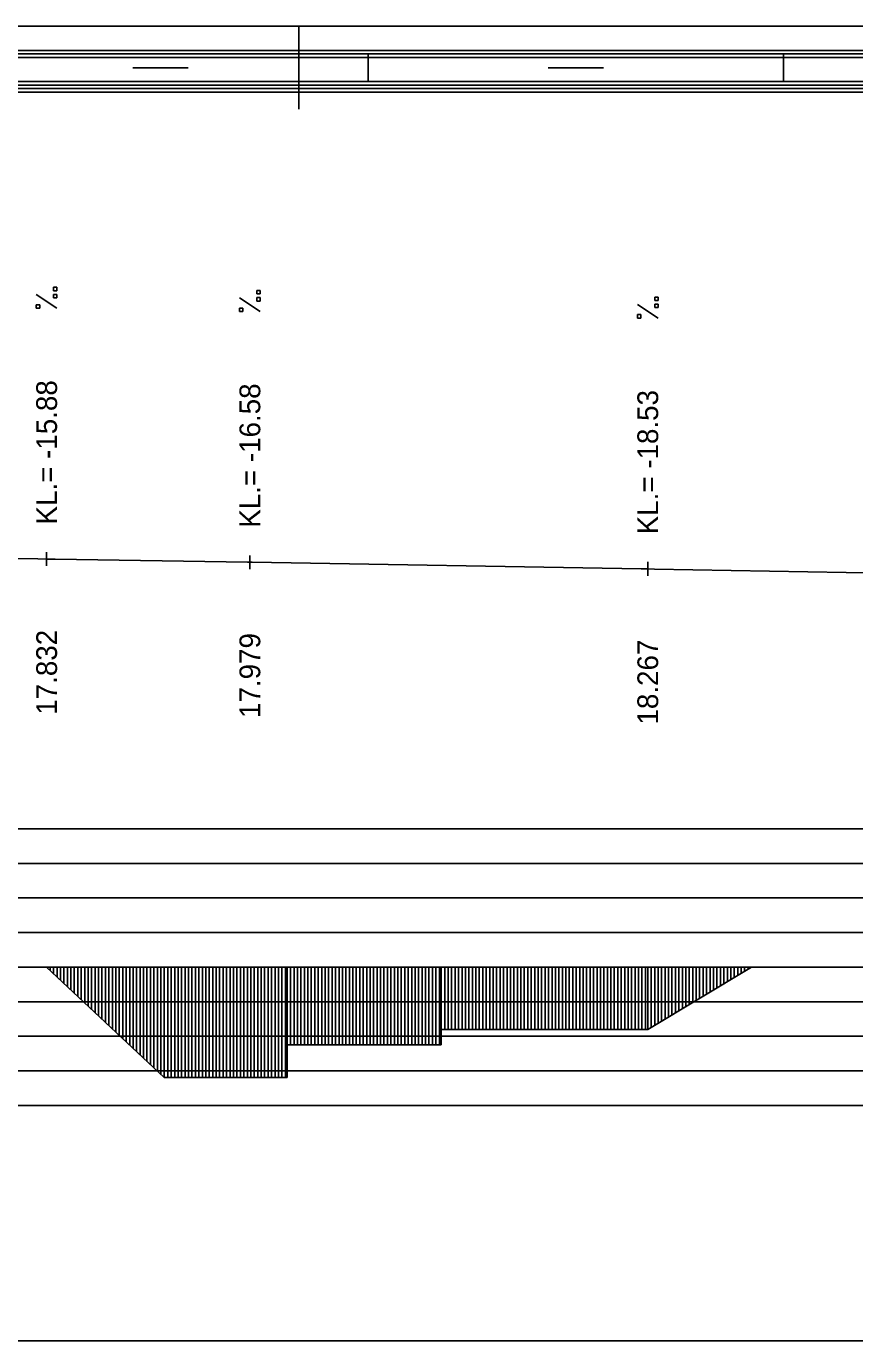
# Model space of a CAD drawing. Extents: x 2 to 10148, y 0 to 380.
# Drawn here: x 2080.3 to 2140.1, y 285 to 380 of the extents above; entities that cross this region are included whole.
import ezdxf

# ---------------------------------------------------------------- set-up
doc = ezdxf.new("R2010")
doc.units = 0
for name, color, linetype in [('NIVELETA_CARA', 7, 'Continuous'), ('NIVELETA_TEXT', 7, 'Continuous'), ('RAM', 7, 'Continuous'), ('ZRYCHL_CARA_C', 7, 'Continuous'), ('ZRYCHL_RASTR', 7, 'Continuous')]:
    doc.layers.add(name, color=color, linetype=linetype)

msp = doc.modelspace()

# ---------------------------------------------------------------- linework, layer by layer
at = {"layer": 'NIVELETA_CARA'}
for p, q in [((2066.966, 341.766), (2081.147, 341.505)), ((2081.147, 341.505), (2081.774, 341.494)), ((2081.774, 340.994), (2081.774, 341.994)), ((2081.774, 341.494), (2082.402, 341.484)), ((2082.402, 341.484), (2096.281, 341.263)), ((2096.281, 341.263), (2096.456, 341.26)), ((2096.456, 340.76), (2096.456, 341.76)), ((2096.456, 341.26), (2096.63, 341.258)), ((2096.63, 341.258), (2124.71, 340.792)), ((2125.198, 340.284), (2125.198, 341.284)), ((2124.71, 340.792), (2125.198, 340.784)), ((2125.198, 340.784), (2125.686, 340.775)), ((2125.686, 340.775), (2153.756, 340.254))]:
    msp.add_line(p, q, dxfattribs=at)
at = {"layer": 'NIVELETA_TEXT'}
for p, q in [((2082.522, 361.137), (2082.275, 361.137)), ((2082.275, 361.137), (2082.275, 360.894)), ((2082.522, 360.889), (2082.522, 361.137)), ((2082.521, 359.621), (2081.027, 360.611)), ((2082.275, 360.894), (2082.279, 360.889)), ((2082.275, 360.889), (2082.522, 360.889)), ((2082.522, 360.626), (2082.275, 360.626)), ((2082.275, 360.626), (2082.275, 360.383)), ((2082.275, 360.383), (2082.279, 360.378)), ((2082.275, 360.378), (2082.522, 360.378)), ((2082.522, 360.378), (2082.522, 360.626)), ((2097.202, 359.388), (2095.708, 360.378)), ((2097.203, 360.904), (2096.956, 360.904)), ((2096.956, 360.904), (2096.956, 360.661)), ((2096.956, 360.661), (2096.961, 360.656)), ((2096.956, 360.656), (2097.203, 360.656)), ((2097.203, 360.393), (2096.956, 360.393)), ((2096.956, 360.393), (2096.956, 360.15)), ((2096.956, 360.15), (2096.961, 360.145)), ((2096.956, 360.145), (2097.203, 360.145)), ((2097.203, 360.656), (2097.203, 360.904)), ((2097.203, 360.145), (2097.203, 360.393)), ((2125.946, 360.427), (2125.698, 360.427)), ((2125.698, 360.427), (2125.698, 360.184)), ((2125.698, 360.184), (2125.703, 360.18)), ((2125.698, 360.18), (2125.946, 360.18)), ((2125.946, 360.18), (2125.946, 360.427)), ((2081.274, 359.868), (2081.027, 359.868)), ((2081.027, 359.868), (2081.027, 359.625)), ((2081.027, 359.625), (2081.032, 359.621)), ((2081.027, 359.621), (2081.274, 359.621)), ((2081.274, 359.621), (2081.274, 359.868)), ((2095.956, 359.635), (2095.708, 359.635)), ((2095.708, 359.635), (2095.708, 359.392)), ((2095.708, 359.392), (2095.713, 359.388)), ((2095.708, 359.388), (2095.956, 359.388)), ((2095.956, 359.388), (2095.956, 359.635)), ((2125.945, 358.911), (2124.451, 359.902)), ((2124.698, 359.159), (2124.451, 359.159)), ((2124.451, 359.159), (2124.451, 358.916)), ((2124.698, 358.911), (2124.698, 359.159)), ((2125.946, 359.916), (2125.698, 359.916)), ((2125.698, 359.916), (2125.698, 359.673)), ((2125.698, 359.673), (2125.703, 359.668)), ((2125.698, 359.668), (2125.946, 359.668)), ((2125.946, 359.668), (2125.946, 359.916)), ((2124.451, 358.916), (2124.456, 358.911)), ((2124.451, 358.911), (2124.698, 358.911))]:
    msp.add_line(p, q, dxfattribs=at)
at = {"layer": 'RAM'}
for p, q in [((2170.827, 380), (1850.83, 380)), ((2100, 374), (2100, 380)), ((2170.827, 378.25), (1850.83, 378.25)), ((2170.827, 378), (1850.83, 378)), ((2170.827, 377.75), (1850.83, 377.75)), ((2105, 376), (2105, 378)), ((2135, 376), (2135, 378)), ((2088, 377), (2092, 377)), ((2118, 377), (2122, 377)), ((2170.827, 376), (1850.83, 376)), ((2170.827, 375.75), (1850.83, 375.75)), ((2170.827, 375.5), (1850.83, 375.5)), ((2170.827, 375.25), (1850.83, 375.25))]:
    msp.add_line(p, q, dxfattribs=at)
at = {"layer": 'ZRYCHL_CARA_C'}
for p, q in [((1850.83, 312), (2170.827, 312)), ((2081.773, 312), (2090.273, 304.018)), ((2082.023, 312), (2082.023, 311.765)), ((2082.273, 312), (2082.273, 311.53)), ((2082.523, 312), (2082.523, 311.296)), ((2082.773, 312), (2082.773, 311.061)), ((2083.023, 312), (2083.023, 310.826)), ((2083.273, 312), (2083.273, 310.591)), ((2083.523, 312), (2083.523, 310.357)), ((2083.773, 312), (2083.773, 310.122)), ((2084.023, 312), (2084.023, 309.887)), ((2084.273, 312), (2084.273, 309.652)), ((2084.523, 312), (2084.523, 309.418)), ((2084.773, 312), (2084.773, 309.183)), ((2085.023, 312), (2085.023, 308.948)), ((2085.273, 312), (2085.273, 308.713)), ((2085.523, 312), (2085.523, 308.479)), ((2085.773, 312), (2085.773, 308.244)), ((2086.023, 312), (2086.023, 308.009)), ((2086.273, 312), (2086.273, 307.774)), ((2086.523, 312), (2086.523, 307.54)), ((2086.773, 312), (2086.773, 307.305)), ((2087.023, 312), (2087.023, 307.07)), ((2087.273, 312), (2087.273, 306.835)), ((2087.523, 312), (2087.523, 306.6)), ((2087.773, 312), (2087.773, 306.366)), ((2088.023, 312), (2088.023, 306.131)), ((2088.273, 312), (2088.273, 305.896)), ((2088.523, 312), (2088.523, 305.661)), ((2088.773, 312), (2088.773, 305.427)), ((2089.023, 312), (2089.023, 305.192)), ((2089.273, 312), (2089.273, 304.957)), ((2089.523, 312), (2089.523, 304.722)), ((2089.773, 312), (2089.773, 304.488)), ((2090.023, 312), (2090.023, 304.253)), ((2090.273, 312), (2090.273, 304.018)), ((2090.523, 312), (2090.523, 304.018)), ((2090.773, 312), (2090.773, 304.018)), ((2091.023, 312), (2091.023, 304.018)), ((2091.273, 312), (2091.273, 304.018)), ((2091.523, 312), (2091.523, 304.018)), ((2091.773, 312), (2091.773, 304.018)), ((2092.023, 312), (2092.023, 304.018)), ((2092.273, 312), (2092.273, 304.018)), ((2092.523, 312), (2092.523, 304.018)), ((2092.773, 312), (2092.773, 304.018)), ((2093.023, 312), (2093.023, 304.018)), ((2093.273, 312), (2093.273, 304.018)), ((2093.523, 312), (2093.523, 304.018)), ((2093.773, 312), (2093.773, 304.018)), ((2094.023, 312), (2094.023, 304.018)), ((2094.273, 312), (2094.273, 304.018)), ((2094.523, 312), (2094.523, 304.018)), ((2094.773, 312), (2094.773, 304.018)), ((2095.023, 312), (2095.023, 304.018)), ((2095.273, 312), (2095.273, 304.018)), ((2095.523, 312), (2095.523, 304.018)), ((2095.773, 312), (2095.773, 304.018)), ((2096.023, 312), (2096.023, 304.018)), ((2096.273, 312), (2096.273, 304.018)), ((2096.523, 312), (2096.523, 304.018)), ((2096.773, 312), (2096.773, 304.018)), ((2097.023, 312), (2097.023, 304.018)), ((2097.273, 312), (2097.273, 304.018)), ((2097.523, 312), (2097.523, 304.018)), ((2097.773, 312), (2097.773, 304.018)), ((2098.023, 312), (2098.023, 304.018)), ((2098.273, 312), (2098.273, 304.018)), ((2098.523, 312), (2098.523, 304.018)), ((2098.773, 312), (2098.773, 304.018)), ((2099.023, 312), (2099.023, 304.018)), ((2099.144, 312), (2099.144, 306.389)), ((2099.394, 312), (2099.394, 306.389)), ((2099.644, 312), (2099.644, 306.389)), ((2099.894, 312), (2099.894, 306.389)), ((2100.144, 312), (2100.144, 306.389)), ((2100.394, 312), (2100.394, 306.389)), ((2100.644, 312), (2100.644, 306.389)), ((2100.894, 312), (2100.894, 306.389)), ((2101.144, 312), (2101.144, 306.389)), ((2101.394, 312), (2101.394, 306.389)), ((2101.644, 312), (2101.644, 306.389)), ((2101.894, 312), (2101.894, 306.389)), ((2102.144, 312), (2102.144, 306.389)), ((2102.394, 312), (2102.394, 306.389)), ((2102.644, 312), (2102.644, 306.389)), ((2102.894, 312), (2102.894, 306.389)), ((2103.144, 312), (2103.144, 306.389)), ((2103.394, 312), (2103.394, 306.389)), ((2103.644, 312), (2103.644, 306.389)), ((2103.894, 312), (2103.894, 306.389)), ((2104.144, 312), (2104.144, 306.389)), ((2104.394, 312), (2104.394, 306.389)), ((2104.644, 312), (2104.644, 306.389)), ((2104.894, 312), (2104.894, 306.389)), ((2105.144, 312), (2105.144, 306.389)), ((2105.394, 312), (2105.394, 306.389)), ((2105.644, 312), (2105.644, 306.389)), ((2105.894, 312), (2105.894, 306.389)), ((2106.144, 312), (2106.144, 306.389)), ((2106.394, 312), (2106.394, 306.389)), ((2106.644, 312), (2106.644, 306.389)), ((2106.894, 312), (2106.894, 306.389)), ((2107.144, 312), (2107.144, 306.389)), ((2107.394, 312), (2107.394, 306.389)), ((2107.644, 312), (2107.644, 306.389)), ((2107.894, 312), (2107.894, 306.389)), ((2108.144, 312), (2108.144, 306.389)), ((2108.394, 312), (2108.394, 306.389)), ((2108.644, 312), (2108.644, 306.389)), ((2108.894, 312), (2108.894, 306.389)), ((2109.144, 312), (2109.144, 306.389)), ((2109.394, 312), (2109.394, 306.389)), ((2109.644, 312), (2109.644, 306.389)), ((2109.894, 312), (2109.894, 306.389)), ((2110.144, 312), (2110.144, 306.389)), ((2110.281, 312), (2110.281, 307.5)), ((2110.531, 312), (2110.531, 307.5)), ((2110.781, 312), (2110.781, 307.5)), ((2111.031, 312), (2111.031, 307.5)), ((2111.281, 312), (2111.281, 307.5)), ((2111.531, 312), (2111.531, 307.5)), ((2111.781, 312), (2111.781, 307.5)), ((2112.031, 312), (2112.031, 307.5)), ((2112.281, 312), (2112.281, 307.5)), ((2112.531, 312), (2112.531, 307.5)), ((2112.781, 312), (2112.781, 307.5)), ((2113.031, 312), (2113.031, 307.5)), ((2113.281, 312), (2113.281, 307.5)), ((2113.531, 312), (2113.531, 307.5)), ((2113.781, 312), (2113.781, 307.5)), ((2114.031, 312), (2114.031, 307.5)), ((2114.281, 312), (2114.281, 307.5)), ((2114.531, 312), (2114.531, 307.5)), ((2114.781, 312), (2114.781, 307.5)), ((2115.031, 312), (2115.031, 307.5)), ((2115.281, 312), (2115.281, 307.5)), ((2115.531, 312), (2115.531, 307.5)), ((2115.781, 312), (2115.781, 307.5)), ((2116.031, 312), (2116.031, 307.5)), ((2116.281, 312), (2116.281, 307.5)), ((2116.531, 312), (2116.531, 307.5)), ((2116.781, 312), (2116.781, 307.5)), ((2117.031, 312), (2117.031, 307.5)), ((2117.281, 312), (2117.281, 307.5)), ((2117.531, 312), (2117.531, 307.5)), ((2117.781, 312), (2117.781, 307.5)), ((2118.031, 312), (2118.031, 307.5)), ((2118.281, 312), (2118.281, 307.5)), ((2118.531, 312), (2118.531, 307.5)), ((2118.781, 312), (2118.781, 307.5)), ((2119.031, 312), (2119.031, 307.5)), ((2119.281, 312), (2119.281, 307.5)), ((2119.531, 312), (2119.531, 307.5)), ((2119.781, 312), (2119.781, 307.5)), ((2120.031, 312), (2120.031, 307.5)), ((2120.281, 312), (2120.281, 307.5)), ((2120.531, 312), (2120.531, 307.5)), ((2120.781, 312), (2120.781, 307.5)), ((2121.031, 312), (2121.031, 307.5)), ((2121.281, 312), (2121.281, 307.5)), ((2121.531, 312), (2121.531, 307.5)), ((2121.781, 312), (2121.781, 307.5)), ((2122.031, 312), (2122.031, 307.5)), ((2122.281, 312), (2122.281, 307.5)), ((2122.531, 312), (2122.531, 307.5)), ((2122.781, 312), (2122.781, 307.5)), ((2123.031, 312), (2123.031, 307.5)), ((2123.281, 312), (2123.281, 307.5)), ((2123.531, 312), (2123.531, 307.5)), ((2123.781, 312), (2123.781, 307.5)), ((2124.031, 312), (2124.031, 307.5)), ((2124.281, 312), (2124.281, 307.5)), ((2124.531, 312), (2124.531, 307.5)), ((2124.781, 312), (2124.781, 307.5)), ((2125.031, 312), (2125.031, 307.5)), ((2125.197, 312), (2125.197, 307.5)), ((2125.197, 307.5), (2132.697, 312)), ((2125.447, 312), (2125.447, 307.65)), ((2125.697, 312), (2125.697, 307.8)), ((2125.947, 312), (2125.947, 307.95)), ((2126.197, 312), (2126.197, 308.1)), ((2126.447, 312), (2126.447, 308.25)), ((2126.697, 312), (2126.697, 308.4)), ((2126.947, 312), (2126.947, 308.55)), ((2127.197, 312), (2127.197, 308.7)), ((2127.447, 312), (2127.447, 308.85)), ((2127.697, 312), (2127.697, 309)), ((2127.947, 312), (2127.947, 309.15)), ((2128.197, 312), (2128.197, 309.3)), ((2128.447, 312), (2128.447, 309.45)), ((2128.697, 312), (2128.697, 309.6)), ((2128.947, 312), (2128.947, 309.75)), ((2129.197, 312), (2129.197, 309.9)), ((2129.447, 312), (2129.447, 310.05)), ((2129.697, 312), (2129.697, 310.2)), ((2129.947, 312), (2129.947, 310.35)), ((2130.197, 312), (2130.197, 310.5)), ((2130.447, 312), (2130.447, 310.65)), ((2130.697, 312), (2130.697, 310.8)), ((2130.947, 312), (2130.947, 310.95)), ((2131.197, 312), (2131.197, 311.1)), ((2131.447, 312), (2131.447, 311.25)), ((2131.697, 312), (2131.697, 311.4)), ((2131.947, 312), (2131.947, 311.55)), ((2132.197, 312), (2132.197, 311.7)), ((2132.447, 312), (2132.447, 311.85)), ((2110.281, 306.389), (2110.281, 307.5)), ((2110.281, 307.5), (2125.197, 307.5)), ((2099.144, 304.018), (2099.144, 306.389)), ((2099.144, 306.389), (2110.281, 306.389)), ((2090.273, 304.018), (2099.144, 304.018))]:
    msp.add_line(p, q, dxfattribs=at)
at = {"layer": 'ZRYCHL_RASTR'}
for p, q in [((2002, 322), (2249.572, 322)), ((2002, 319.5), (2249.572, 319.5)), ((2002, 317), (2249.559, 317)), ((2002, 314.5), (2249.559, 314.5)), ((2002, 309.5), (2197.941, 309.5)), ((2002, 307), (2197.849, 307)), ((2002, 304.5), (2197.765, 304.5)), ((2002, 302), (2197.984, 302)), ((2002, 285), (2251.222, 285))]:
    msp.add_line(p, q, dxfattribs=at)

# ---------------------------------------------------------------- texts
at = {"layer": 'NIVELETA_TEXT'}
for s, p in [('KL.= -15.88', (2082.524, 343.994)), ('KL.= -16.58', (2097.206, 343.76)), ('KL.= -18.53', (2125.948, 343.284)), ('17.832', (2082.524, 330.244)), ('17.979', (2097.206, 330.01)), ('18.267', (2125.948, 329.534))]:
    msp.add_text(s, height=1.5, rotation=90, dxfattribs=at).set_placement(p)

doc.saveas('drawing.dxf')
